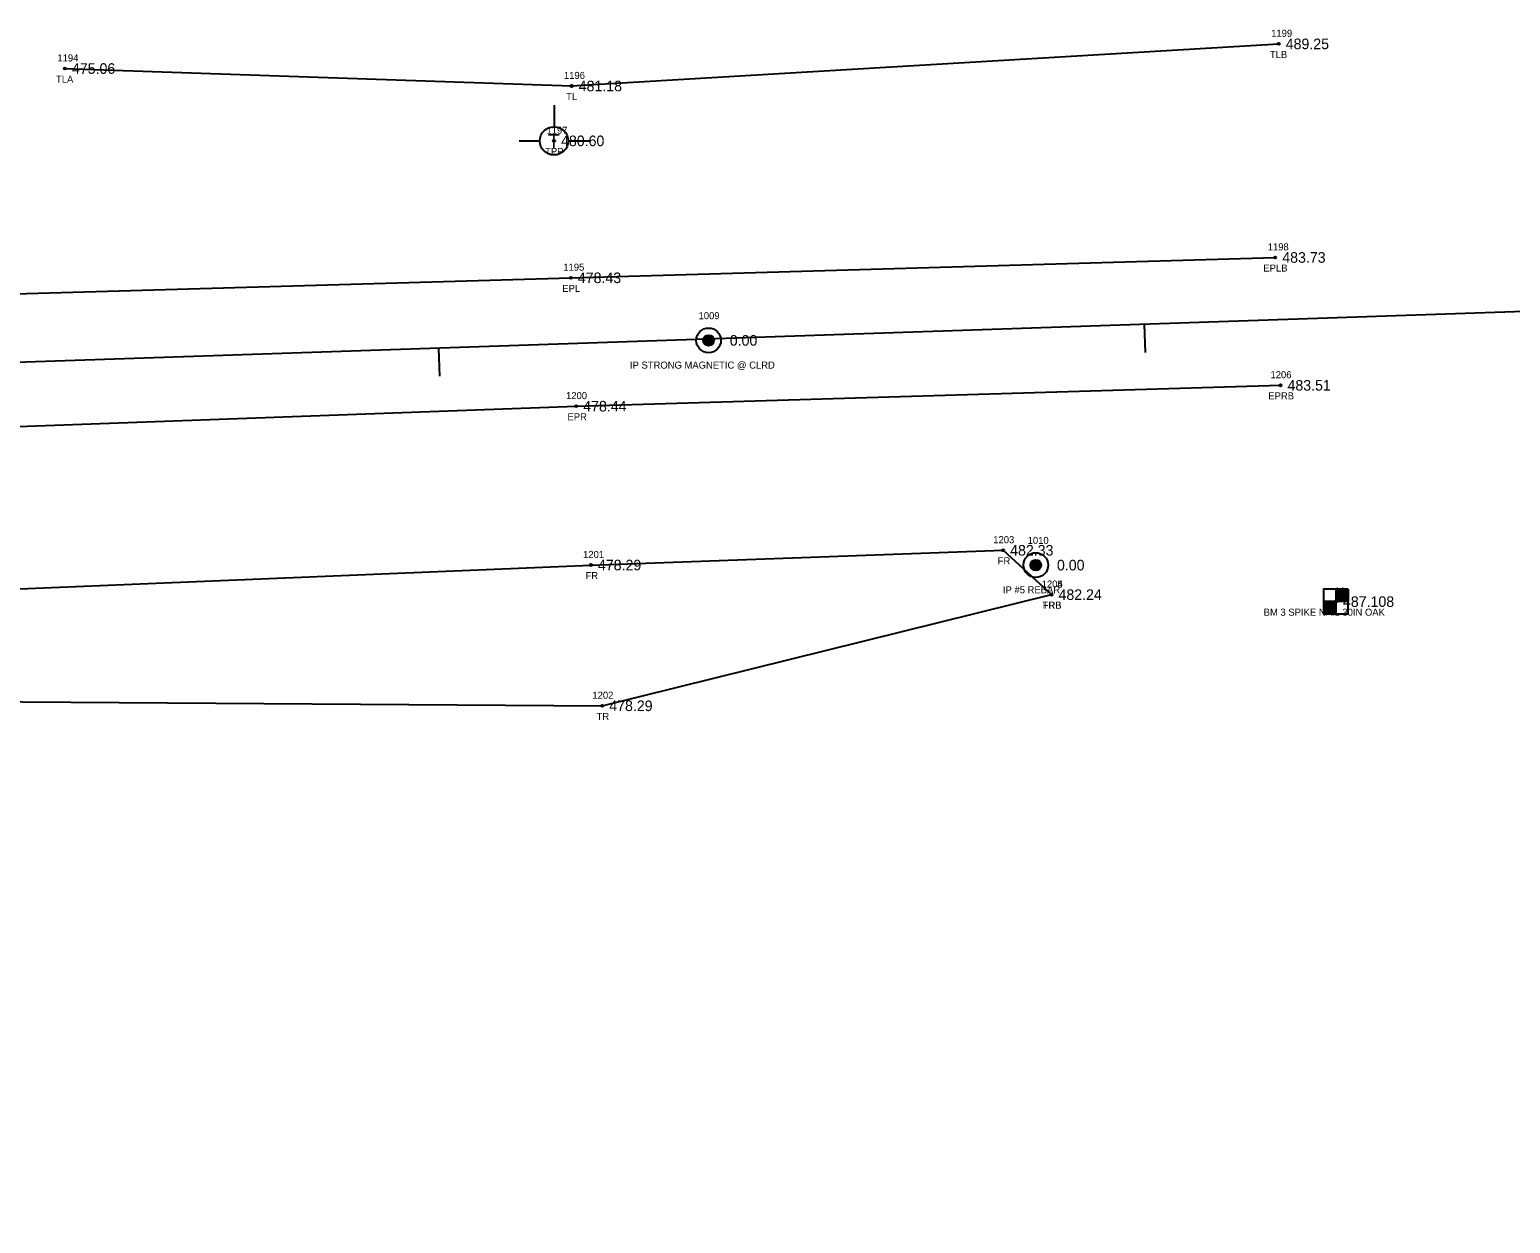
# Model space of a CAD drawing. Extents: x 1784103 to 1787401, y 770251 to 771298.
# Drawn here: x 1786401.6 to 1786611.4, y 770752.9 to 770921.9 of the extents above; entities that cross this region are included whole.
import ezdxf

# ---------------------------------------------------------------- set-up
doc = ezdxf.new("R2010")
doc.units = 0
for name, color, linetype in [('RD_EX_DV_Prop_txCode', 7, 'Continuous'), ('RD_EX_DV_PropPin', 7, 'Continuous'), ('RD_EX_Fence_Other', 7, 'Continuous'), ('RD_EX_Fence_Other_txCode', 7, 'Continuous'), ('RD_EX_Road', 7, 'Continuous'), ('RD_EX_Road_txCode', 7, 'Continuous'), ('RD_EX_TX_DV_Prop_ELEV', 7, 'Continuous'), ('RD_EX_TX_Fence_Other_ELEV', 7, 'Continuous'), ('RD_EX_TX_Road_ELEV', 7, 'Continuous'), ('RD_EX_TX_UT_ELEV', 7, 'Continuous'), ('RD_EX_TX_VEG_ELEV', 7, 'Continuous'), ('RD_EX_UT', 7, 'Continuous'), ('RD_EX_UT_txCode', 7, 'Continuous'), ('RD_EX_VEG', 7, 'Continuous'), ('RD_EX_VEG_txCode', 7, 'Continuous'), ('RD_HC_Cl', 7, 'Continuous'), ('RD_HC_Data_Tic', 7, 'Continuous'), ('RD_HC_Survey', 7, 'Continuous'), ('RD_HC_Survey_ELEV', 7, 'Continuous'), ('RD_HC_Survey_txCode', 7, 'Continuous'), ('RD_SMD_Locator', 7, 'Continuous')]:
    doc.layers.add(name, color=color, linetype=linetype)

msp = doc.modelspace()

# ---------------------------------------------------------------- linework, layer by layer
at = {"layer": 'RD_EX_DV_PropPin'}
for p, q in [((1786497.04, 770877.69), (1786497.04, 770878.08)), ((1786497.07, 770877.59), (1786497.07, 770878.19)), ((1786497.11, 770877.52), (1786497.11, 770878.26)), ((1786497.14, 770877.46), (1786497.14, 770878.32)), ((1786497.18, 770877.41), (1786497.18, 770878.36)), ((1786497.21, 770877.37), (1786497.21, 770878.4)), ((1786497.25, 770877.34), (1786497.25, 770878.44)), ((1786497.28, 770877.31), (1786497.28, 770878.47)), ((1786497.32, 770877.28), (1786497.32, 770878.5)), ((1786497.35, 770877.25), (1786497.35, 770878.52)), ((1786497.39, 770877.23), (1786497.39, 770878.54)), ((1786497.42, 770877.21), (1786497.42, 770878.56)), ((1786497.46, 770877.2), (1786497.46, 770878.58)), ((1786497.49, 770877.18), (1786497.49, 770878.6)), ((1786497.53, 770877.17), (1786497.53, 770878.61)), ((1786497.56, 770877.16), (1786497.56, 770878.62)), ((1786497.6, 770877.15), (1786497.6, 770878.63)), ((1786497.63, 770877.14), (1786497.63, 770878.64)), ((1786497.67, 770877.13), (1786497.67, 770878.64)), ((1786497.7, 770877.13), (1786497.7, 770878.65)), ((1786497.74, 770877.13), (1786497.74, 770878.65)), ((1786497.77, 770877.13), (1786497.77, 770878.65)), ((1786497.81, 770877.13), (1786497.81, 770878.65)), ((1786497.84, 770877.13), (1786497.84, 770878.65)), ((1786497.88, 770877.13), (1786497.88, 770878.64)), ((1786497.91, 770877.14), (1786497.91, 770878.64)), ((1786497.95, 770877.15), (1786497.95, 770878.63)), ((1786497.98, 770877.16), (1786497.98, 770878.62)), ((1786498.02, 770877.17), (1786498.02, 770878.61)), ((1786498.05, 770877.18), (1786498.05, 770878.6)), ((1786498.09, 770877.2), (1786498.09, 770878.58)), ((1786498.12, 770877.21), (1786498.12, 770878.56)), ((1786498.16, 770877.23), (1786498.16, 770878.54)), ((1786498.19, 770877.25), (1786498.19, 770878.52)), ((1786498.23, 770877.28), (1786498.23, 770878.5)), ((1786498.26, 770877.31), (1786498.26, 770878.47)), ((1786498.3, 770877.34), (1786498.3, 770878.44)), ((1786498.33, 770877.37), (1786498.33, 770878.4)), ((1786498.37, 770877.41), (1786498.37, 770878.36)), ((1786498.4, 770877.46), (1786498.4, 770878.32)), ((1786498.44, 770877.52), (1786498.44, 770878.26)), ((1786498.47, 770877.59), (1786498.47, 770878.19)), ((1786498.51, 770877.69), (1786498.51, 770878.08)), ((1786543.38, 770845.87), (1786543.38, 770846.26)), ((1786543.42, 770845.77), (1786543.42, 770846.37)), ((1786543.45, 770845.7), (1786543.45, 770846.44)), ((1786543.49, 770845.64), (1786543.49, 770846.49)), ((1786543.52, 770845.59), (1786543.52, 770846.54)), ((1786543.56, 770845.55), (1786543.56, 770846.58)), ((1786543.59, 770845.52), (1786543.59, 770846.62)), ((1786543.63, 770845.49), (1786543.63, 770846.65)), ((1786543.66, 770845.46), (1786543.66, 770846.68)), ((1786543.7, 770845.43), (1786543.7, 770846.7)), ((1786543.73, 770845.41), (1786543.73, 770846.72)), ((1786543.77, 770845.39), (1786543.77, 770846.74)), ((1786543.8, 770845.38), (1786543.8, 770846.76)), ((1786543.84, 770845.36), (1786543.84, 770846.78)), ((1786543.87, 770845.35), (1786543.87, 770846.79)), ((1786543.91, 770845.34), (1786543.91, 770846.8)), ((1786543.94, 770845.33), (1786543.94, 770846.81)), ((1786543.98, 770845.32), (1786543.98, 770846.82)), ((1786544.01, 770845.31), (1786544.01, 770846.82)), ((1786544.05, 770845.31), (1786544.05, 770846.83)), ((1786544.08, 770845.31), (1786544.08, 770846.83)), ((1786544.12, 770845.31), (1786544.12, 770846.83)), ((1786544.15, 770845.31), (1786544.15, 770846.83)), ((1786544.19, 770845.31), (1786544.19, 770846.83)), ((1786544.22, 770845.31), (1786544.22, 770846.82)), ((1786544.26, 770845.32), (1786544.26, 770846.82)), ((1786544.29, 770845.33), (1786544.29, 770846.81)), ((1786544.33, 770845.34), (1786544.33, 770846.8)), ((1786544.36, 770845.35), (1786544.36, 770846.79)), ((1786544.4, 770845.36), (1786544.4, 770846.78)), ((1786544.43, 770845.38), (1786544.43, 770846.76)), ((1786544.47, 770845.39), (1786544.47, 770846.74)), ((1786544.5, 770845.41), (1786544.5, 770846.72)), ((1786544.54, 770845.43), (1786544.54, 770846.7)), ((1786544.57, 770845.46), (1786544.57, 770846.68)), ((1786544.61, 770845.49), (1786544.61, 770846.65)), ((1786544.64, 770845.52), (1786544.64, 770846.62)), ((1786544.68, 770845.55), (1786544.68, 770846.58)), ((1786544.71, 770845.59), (1786544.71, 770846.54)), ((1786544.75, 770845.64), (1786544.75, 770846.49)), ((1786544.78, 770845.7), (1786544.78, 770846.44)), ((1786544.82, 770845.77), (1786544.82, 770846.37)), ((1786544.85, 770845.87), (1786544.85, 770846.26))]:
    msp.add_line(p, q, dxfattribs=at)
for centre, radius in [((1786497.77, 770877.89), 1.75), ((1786497.77, 770877.89), 0.761), ((1786544.12, 770846.07), 1.75), ((1786544.12, 770846.07), 0.761)]:
    msp.add_circle(centre, radius, dxfattribs=at)
at = {"layer": 'RD_EX_Fence_Other'}
msp.add_lwpolyline([(1785232.56, 770784.32), (1785243.65, 770809.45), (1785281.87, 770810.97), (1785330.77, 770810.35), (1785381.35, 770812.32), (1785481.48, 770815.35), (1785580.21, 770817.42), (1785680.43, 770820.14), (1785794.9, 770821.68), (1785847.9, 770822.69), (1785879.84, 770822.3), (1785979.43, 770826.69), (1786080.46, 770830.52), (1786182.98, 770833.3), (1786235.76, 770836.16), (1786247.48, 770836.31), (1786280.27, 770837.57), (1786379.57, 770841.87), (1786481.1, 770846.08), (1786539.49, 770848.17), (1786546.34, 770841.89)], dxfattribs=at)
at = {"layer": 'RD_EX_Road'}
for points in [[(1785824.57, 770864.86), (1785879.1, 770866.73), (1785977.08, 770869.67), (1786078.78, 770873.52), (1786179.09, 770876.83), (1786278.08, 770880.28), (1786358.72, 770883.31), (1786381.38, 770883.94), (1786478.25, 770886.75), (1786578.04, 770889.63)], [(1785825.31, 770845.6), (1785879.29, 770848.18), (1785979.17, 770851.29), (1786079.29, 770854.66), (1786178.79, 770858.1), (1786233.56, 770860.16), (1786246.2, 770860.52), (1786278.61, 770861.3), (1786379.15, 770864.94), (1786479.01, 770868.57), (1786578.78, 770871.53)]]:
    msp.add_lwpolyline(points, dxfattribs=at)
at = {"layer": 'RD_EX_UT'}
for p, q in [((1786475.87, 770911.21), (1786475.87, 770908.14)), ((1786470.94, 770906.16), (1786473.87, 770906.16)), ((1786477.87, 770906.16), (1786480.94, 770906.16))]:
    msp.add_line(p, q, dxfattribs=at)
msp.add_circle((1786475.87, 770906.14), 2, dxfattribs=at)
at = {"layer": 'RD_EX_VEG'}
for points in [[(1786406.58, 770916.38), (1786478.37, 770913.91), (1786578.53, 770919.87)], [(1785886.65, 770752.86), (1785892.37, 770814.33), (1785979.57, 770818.93), (1786081.14, 770815.54), (1786184.19, 770823.37), (1786281.19, 770817.59), (1786379.98, 770826.87), (1786482.7, 770826.15), (1786546.34, 770841.89)]]:
    msp.add_lwpolyline(points, dxfattribs=at)
at = {"layer": 'RD_HC_Cl'}
msp.add_line((1787025.56, 770895.93), (1785279.14, 770836.9), dxfattribs=at)
at = {"layer": 'RD_HC_Data_Tic'}
for p, q in [((1786559.47, 770880.18), (1786559.61, 770876.18)), ((1786459.53, 770876.8), (1786459.66, 770872.8))]:
    msp.add_line(p, q, dxfattribs=at)
at = {"layer": 'RD_HC_Survey'}
for p, q in [((1786586.64, 770842.65), (1786586.64, 770839.15)), ((1786586.66, 770842.65), (1786586.66, 770840.9)), ((1786586.69, 770842.65), (1786586.69, 770840.9)), ((1786586.71, 770842.65), (1786586.71, 770840.9)), ((1786586.74, 770842.65), (1786586.74, 770840.9)), ((1786586.76, 770842.65), (1786586.76, 770840.9)), ((1786586.78, 770842.65), (1786586.78, 770840.9)), ((1786586.81, 770842.65), (1786586.81, 770840.9)), ((1786586.83, 770842.65), (1786586.83, 770840.9)), ((1786586.86, 770842.65), (1786586.86, 770840.9)), ((1786586.88, 770842.65), (1786586.88, 770840.9)), ((1786586.91, 770842.65), (1786586.91, 770840.9)), ((1786586.93, 770842.65), (1786586.93, 770840.9)), ((1786586.96, 770842.65), (1786586.96, 770840.9)), ((1786586.98, 770842.65), (1786586.98, 770840.9)), ((1786587.01, 770842.65), (1786587.01, 770840.9)), ((1786587.03, 770842.65), (1786587.03, 770840.9)), ((1786587.06, 770842.65), (1786587.06, 770840.9)), ((1786587.08, 770842.65), (1786587.08, 770840.9)), ((1786587.11, 770842.65), (1786587.11, 770840.9)), ((1786587.13, 770842.65), (1786587.13, 770840.9)), ((1786587.16, 770842.65), (1786587.16, 770840.9)), ((1786587.18, 770842.65), (1786587.18, 770840.9)), ((1786587.21, 770842.65), (1786587.21, 770840.9)), ((1786587.23, 770842.65), (1786587.23, 770840.9)), ((1786587.25, 770842.65), (1786587.25, 770840.9)), ((1786587.28, 770842.65), (1786587.28, 770840.9)), ((1786587.3, 770842.65), (1786587.3, 770840.9)), ((1786587.33, 770842.65), (1786587.33, 770840.9)), ((1786587.35, 770842.65), (1786587.35, 770840.9)), ((1786587.38, 770842.65), (1786587.38, 770840.9)), ((1786587.4, 770842.65), (1786587.4, 770840.9)), ((1786587.43, 770842.65), (1786587.43, 770840.9)), ((1786587.45, 770842.65), (1786587.45, 770840.9)), ((1786587.48, 770842.65), (1786587.48, 770840.9)), ((1786587.5, 770842.65), (1786587.5, 770840.9)), ((1786587.53, 770842.65), (1786587.53, 770840.9)), ((1786587.55, 770842.65), (1786587.55, 770840.9)), ((1786587.58, 770842.65), (1786587.58, 770840.9)), ((1786587.6, 770842.65), (1786587.6, 770840.9)), ((1786587.63, 770842.65), (1786587.63, 770840.9)), ((1786587.65, 770842.65), (1786587.65, 770840.9)), ((1786587.68, 770842.65), (1786587.68, 770840.9)), ((1786587.7, 770842.65), (1786587.7, 770840.9)), ((1786587.73, 770842.65), (1786587.73, 770840.9)), ((1786587.75, 770842.65), (1786587.75, 770840.9)), ((1786587.77, 770842.65), (1786587.77, 770840.9)), ((1786587.8, 770842.65), (1786587.8, 770840.9)), ((1786587.82, 770842.65), (1786587.82, 770840.9)), ((1786587.85, 770842.65), (1786587.85, 770840.9)), ((1786587.87, 770842.65), (1786587.87, 770840.9)), ((1786587.9, 770842.65), (1786587.9, 770840.9)), ((1786587.92, 770842.65), (1786587.92, 770840.9)), ((1786587.95, 770842.65), (1786587.95, 770840.9)), ((1786587.97, 770842.65), (1786587.97, 770840.9)), ((1786588, 770842.65), (1786588, 770840.9)), ((1786588.02, 770842.65), (1786588.02, 770840.9)), ((1786588.05, 770842.65), (1786588.05, 770840.9)), ((1786588.07, 770842.65), (1786588.07, 770840.9)), ((1786588.1, 770842.65), (1786588.1, 770840.9)), ((1786588.12, 770842.65), (1786588.12, 770840.9)), ((1786588.15, 770842.65), (1786588.15, 770840.9)), ((1786588.17, 770842.65), (1786588.17, 770840.9)), ((1786588.2, 770842.65), (1786588.2, 770840.9)), ((1786588.22, 770842.65), (1786588.22, 770840.9)), ((1786588.24, 770842.65), (1786588.24, 770840.9)), ((1786588.27, 770842.65), (1786588.27, 770840.9)), ((1786588.29, 770842.65), (1786588.29, 770840.9)), ((1786588.32, 770842.65), (1786588.32, 770840.9)), ((1786588.34, 770842.65), (1786588.34, 770840.9)), ((1786588.37, 770842.65), (1786588.37, 770840.9)), ((1786588.39, 770840.9), (1786584.89, 770840.9)), ((1786584.89, 770840.9), (1786584.89, 770839.15)), ((1786584.92, 770840.9), (1786584.92, 770839.15)), ((1786584.94, 770840.9), (1786584.94, 770839.15)), ((1786584.97, 770840.9), (1786584.97, 770839.15)), ((1786584.99, 770840.9), (1786584.99, 770839.15)), ((1786585.02, 770840.9), (1786585.02, 770839.15)), ((1786585.04, 770840.9), (1786585.04, 770839.15)), ((1786585.07, 770840.9), (1786585.07, 770839.15)), ((1786585.09, 770840.9), (1786585.09, 770839.15)), ((1786585.12, 770840.9), (1786585.12, 770839.15)), ((1786585.14, 770840.9), (1786585.14, 770839.15)), ((1786585.17, 770840.9), (1786585.17, 770839.15)), ((1786585.19, 770840.9), (1786585.19, 770839.15)), ((1786585.22, 770840.9), (1786585.22, 770839.15)), ((1786585.24, 770840.9), (1786585.24, 770839.15)), ((1786585.26, 770840.9), (1786585.26, 770839.15)), ((1786585.29, 770840.9), (1786585.29, 770839.15)), ((1786585.31, 770840.9), (1786585.31, 770839.15)), ((1786585.34, 770840.9), (1786585.34, 770839.15)), ((1786585.36, 770840.9), (1786585.36, 770839.15)), ((1786585.39, 770840.9), (1786585.39, 770839.15)), ((1786585.41, 770840.9), (1786585.41, 770839.15)), ((1786585.44, 770840.9), (1786585.44, 770839.15)), ((1786585.46, 770840.9), (1786585.46, 770839.15)), ((1786585.49, 770840.9), (1786585.49, 770839.15)), ((1786585.51, 770840.9), (1786585.51, 770839.15)), ((1786585.54, 770840.9), (1786585.54, 770839.15)), ((1786585.56, 770840.9), (1786585.56, 770839.15)), ((1786585.59, 770840.9), (1786585.59, 770839.15)), ((1786585.61, 770840.9), (1786585.61, 770839.15)), ((1786585.64, 770840.9), (1786585.64, 770839.15)), ((1786585.66, 770840.9), (1786585.66, 770839.15)), ((1786585.69, 770840.9), (1786585.69, 770839.15)), ((1786585.71, 770840.9), (1786585.71, 770839.15)), ((1786585.73, 770840.9), (1786585.73, 770839.15)), ((1786585.76, 770840.9), (1786585.76, 770839.15)), ((1786585.78, 770840.9), (1786585.78, 770839.15)), ((1786585.81, 770840.9), (1786585.81, 770839.15)), ((1786585.83, 770840.9), (1786585.83, 770839.15)), ((1786585.86, 770840.9), (1786585.86, 770839.15)), ((1786585.88, 770840.9), (1786585.88, 770839.15)), ((1786585.91, 770840.9), (1786585.91, 770839.15)), ((1786585.93, 770840.9), (1786585.93, 770839.15)), ((1786585.96, 770840.9), (1786585.96, 770839.15)), ((1786585.98, 770840.9), (1786585.98, 770839.15)), ((1786586.01, 770840.9), (1786586.01, 770839.15)), ((1786586.03, 770840.9), (1786586.03, 770839.15)), ((1786586.06, 770840.9), (1786586.06, 770839.15)), ((1786586.08, 770840.9), (1786586.08, 770839.15)), ((1786586.11, 770840.9), (1786586.11, 770839.15)), ((1786586.13, 770840.9), (1786586.13, 770839.15)), ((1786586.16, 770840.9), (1786586.16, 770839.15)), ((1786586.18, 770840.9), (1786586.18, 770839.15)), ((1786586.2, 770840.9), (1786586.2, 770839.15)), ((1786586.23, 770840.9), (1786586.23, 770839.15)), ((1786586.25, 770840.9), (1786586.25, 770839.15)), ((1786586.28, 770840.9), (1786586.28, 770839.15)), ((1786586.3, 770840.9), (1786586.3, 770839.15)), ((1786586.33, 770840.9), (1786586.33, 770839.15)), ((1786586.35, 770840.9), (1786586.35, 770839.15)), ((1786586.38, 770840.9), (1786586.38, 770839.15)), ((1786586.4, 770840.9), (1786586.4, 770839.15)), ((1786586.43, 770840.9), (1786586.43, 770839.15)), ((1786586.45, 770840.9), (1786586.45, 770839.15)), ((1786586.48, 770840.9), (1786586.48, 770839.15)), ((1786586.5, 770840.9), (1786586.5, 770839.15)), ((1786586.53, 770840.9), (1786586.53, 770839.15)), ((1786586.55, 770840.9), (1786586.55, 770839.15)), ((1786586.58, 770840.9), (1786586.58, 770839.15)), ((1786586.6, 770840.9), (1786586.6, 770839.15)), ((1786586.63, 770840.9), (1786586.63, 770839.15))]:
    msp.add_line(p, q, dxfattribs=at)
msp.add_lwpolyline([(1786588.39, 770842.65), (1786584.89, 770842.65), (1786584.89, 770839.15), (1786588.39, 770839.15)], close=True, dxfattribs=at)
at = {"layer": 'RD_SMD_Locator'}
for centre in [(1786578.53, 770919.87), (1786406.58, 770916.38), (1786478.37, 770913.91), (1786475.87, 770906.14), (1786578.04, 770889.63), (1786478.25, 770886.75), (1786497.77, 770877.89), (1786578.78, 770871.53), (1786479.01, 770868.57), (1786539.49, 770848.17), (1786481.1, 770846.08), (1786544.12, 770846.07), (1786546.34, 770841.89), (1786546.34, 770841.89), (1786586.64, 770840.9), (1786482.7, 770826.15)]:
    msp.add_circle(centre, 0.15, dxfattribs=at)

# ---------------------------------------------------------------- texts
at = {"layer": 'RD_EX_DV_Prop_txCode'}
for s, p in [('1009', (1786496.35, 770880.89)), ('IP STRONG MAGNETIC @ CLRD', (1786486.63, 770873.89)), ('1010', (1786542.97, 770849.07)), ('IP #5 REBAR', (1786539.47, 770842.07))]:
    msp.add_text(s, height=1, dxfattribs=at).set_placement(p)
at = {"layer": 'RD_EX_Fence_Other_txCode'}
for s, p in [('1203', (1786538.1, 770849.17)), ('1201', (1786479.99, 770847.08)), ('FR', (1786538.73, 770846.17)), ('FR', (1786480.34, 770844.08)), ('1204', (1786544.96, 770842.89)), ('FRB', (1786545.11, 770839.89))]:
    msp.add_text(s, height=1, dxfattribs=at).set_placement(p)
at = {"layer": 'RD_EX_Road_txCode'}
for s, p in [('1198', (1786576.98, 770890.63)), ('1195', (1786477.19, 770887.75)), ('EPLB', (1786576.36, 770887.63)), ('EPL', (1786477.04, 770884.75)), ('1206', (1786577.37, 770872.53)), ('1200', (1786477.58, 770869.57)), ('EPRB', (1786577.07, 770869.53)), ('EPR', (1786477.78, 770866.57))]:
    msp.add_text(s, height=1, dxfattribs=at).set_placement(p)
at = {"layer": 'RD_EX_TX_DV_Prop_ELEV'}
for p in [(1786500.77, 770877.14), (1786547.12, 770845.32)]:
    msp.add_text('0.00', height=1.5, dxfattribs=at).set_placement(p)
at = {"layer": 'RD_EX_TX_Fence_Other_ELEV'}
for s, p in [('482.33', (1786540.49, 770847.42)), ('478.29', (1786482.1, 770845.33)), ('482.24', (1786547.34, 770841.14))]:
    msp.add_text(s, height=1.5, dxfattribs=at).set_placement(p)
at = {"layer": 'RD_EX_TX_Road_ELEV'}
for s, p in [('483.73', (1786579.04, 770888.88)), ('478.43', (1786479.25, 770886)), ('483.51', (1786579.78, 770870.78)), ('478.44', (1786480.01, 770867.82))]:
    msp.add_text(s, height=1.5, dxfattribs=at).set_placement(p)
at = {"layer": 'RD_EX_TX_UT_ELEV'}
msp.add_text('480.60', height=1.5, dxfattribs=at).set_placement((1786476.87, 770905.39))
at = {"layer": 'RD_EX_TX_VEG_ELEV'}
for s, p in [('489.25', (1786579.53, 770919.12)), ('475.06', (1786407.58, 770915.63)), ('481.18', (1786479.37, 770913.16)), ('482.24', (1786547.34, 770841.14)), ('478.29', (1786483.7, 770825.4))]:
    msp.add_text(s, height=1.5, dxfattribs=at).set_placement(p)
at = {"layer": 'RD_EX_UT'}
msp.add_text('T', height=2, dxfattribs=at).set_placement((1786475.03, 770905.1))
at = {"layer": 'RD_EX_UT_txCode'}
for s, p in [('1197', (1786474.81, 770907.14)), ('TPP', (1786474.61, 770904.14))]:
    msp.add_text(s, height=1, dxfattribs=at).set_placement(p)
at = {"layer": 'RD_EX_VEG_txCode'}
for s, p in [('1199', (1786577.47, 770920.87)), ('1194', (1786405.52, 770917.38)), ('TLB', (1786577.29, 770917.87)), ('TLA', (1786405.32, 770914.38)), ('1196', (1786477.28, 770914.91)), ('TL', (1786477.59, 770911.91)), ('1205', (1786544.96, 770842.89)), ('TRB', (1786545.07, 770839.89)), ('1202', (1786481.31, 770827.15)), ('TR', (1786481.9, 770824.15))]:
    msp.add_text(s, height=1, dxfattribs=at).set_placement(p)
at = {"layer": 'RD_HC_Survey_ELEV'}
msp.add_text('487.108', height=1.5, dxfattribs=at).set_placement((1786587.64, 770840.15))
at = {"layer": 'RD_HC_Survey_txCode'}
for s, p in [('11', (1786586.48, 770841.9)), ('BM 3 SPIKE NAIL 30IN OAK', (1786576.41, 770838.9))]:
    msp.add_text(s, height=1, dxfattribs=at).set_placement(p)

doc.saveas('drawing.dxf')
